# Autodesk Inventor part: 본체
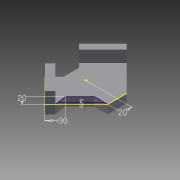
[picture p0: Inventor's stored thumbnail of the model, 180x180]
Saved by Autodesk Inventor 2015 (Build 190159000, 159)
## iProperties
Created: 2020-05
Part Number: 본체
Material: 일반
Document SubType Name: Modeling
Designer: now
Density: 1 g/cm^3
Appearance: 기본값
Author: now
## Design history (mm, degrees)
sketch "스케치2"
  geometry: L1 (-84.853, 0)-(0, 84.853); L2 (0, 84.853)-(84.853, 0); L3 (84.853, 0)-(0, -84.853); L4 (0, -84.853)-(-84.853, 0); L5 (64.853, -20)-(64.853, 20); L6 (-30.147, -16.005)-(-30.147, 16.005); L7 (-30.147, 16.005)-(-49.497, 35.355); L8 (-49.497, -35.355)-(-30.147, -16.005); 1 further point
  constraints: 16 end point, 5 parallel, 4 point on line, 1 perpendicular, 1 vertical, 1 vertical alignment
  dimensions: "d6" = 120 distance of L1.end L2.end; "d7" = 120 distance of L1.start L1.end; "d8" = 60 distance from line of point (0, 0) L4; "d9" = 60 distance from line of L3 point (0, 0); "d10" = 20 distance from line of L5 L2.end; "d11" = 95 distance between parallel lines of L5 L6; "d13" = 50 distance between parallel lines of L4 L7; "d14" = 50 distance between parallel lines of L1 L8
extrude "돌출1" new body sketch "스케치2" distance "d15" = 18; taper "d16" = 0 deg
sketch "스케치3"
  geometry: L1 (0, 84.853)-(-49.497, 35.355) reference; L2 (-49.497, 35.355)-(-30.147, 16.005) reference; L3 (-30.147, -16.005)-(-49.497, -35.355) reference; L4 (-49.497, -35.355)-(0, -84.853) reference; L5 (0, -84.853)-(64.853, -20) reference; L6 (64.853, 20)-(0, 84.853) reference; L7 (10.607, 74.246)-(-38.891, 24.749); L8 (-38.891, -24.749)-(10.607, -74.246); 1 further point
  constraints: 4 end point, 4 point on line, 2 parallel
  dimensions: "d17" = 15 distance between parallel lines of L4 L8; "d18" = 15 distance between parallel lines of L1 L7
extrude "돌출2" join sketch "스케치3" distance "d19" = 24; taper "d20" = 0 deg
sketch "스케치4"
  geometry: L1 (10.607, -74.246)-(64.853, -20) reference; L2 (64.853, -20)-(64.853, 20) reference; L3 (64.853, -20)-(36.569, -20); L4 (36.569, -20)-(7.071, -49.497); L5 (7.071, -49.497)-(10.607, -74.246); L6 (0, -84.853)-(10.607, -74.246) reference; L7 (-49.497, -35.355)-(0, -84.853) reference; L8 (9.723, -68.059)-(57.782, -20); 1 further point
  constraints: 8 end point, 3 point on line, 2 parallel, 1 horizontal
  dimensions: "d21" = 20 distance from line of point (0, 0) L3; "d23" = 30 distance from line of L7 L4.end; "d25" = 20 distance between parallel lines of L1 L4; "d26" = 5 distance between parallel lines of L1 L8
extrude "돌출3" cut sketch "스케치4" stored distance "d27" = 24; taper "d28" = 0 deg
node "솔리드1"
